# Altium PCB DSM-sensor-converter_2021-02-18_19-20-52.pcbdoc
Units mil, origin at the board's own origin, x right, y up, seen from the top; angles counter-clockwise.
Board outline 2250 x 2394.57 mil, 2 copper layers (Top Layer, Bottom Layer); 9 components, 9 nets, 34 pads, 1 vias.
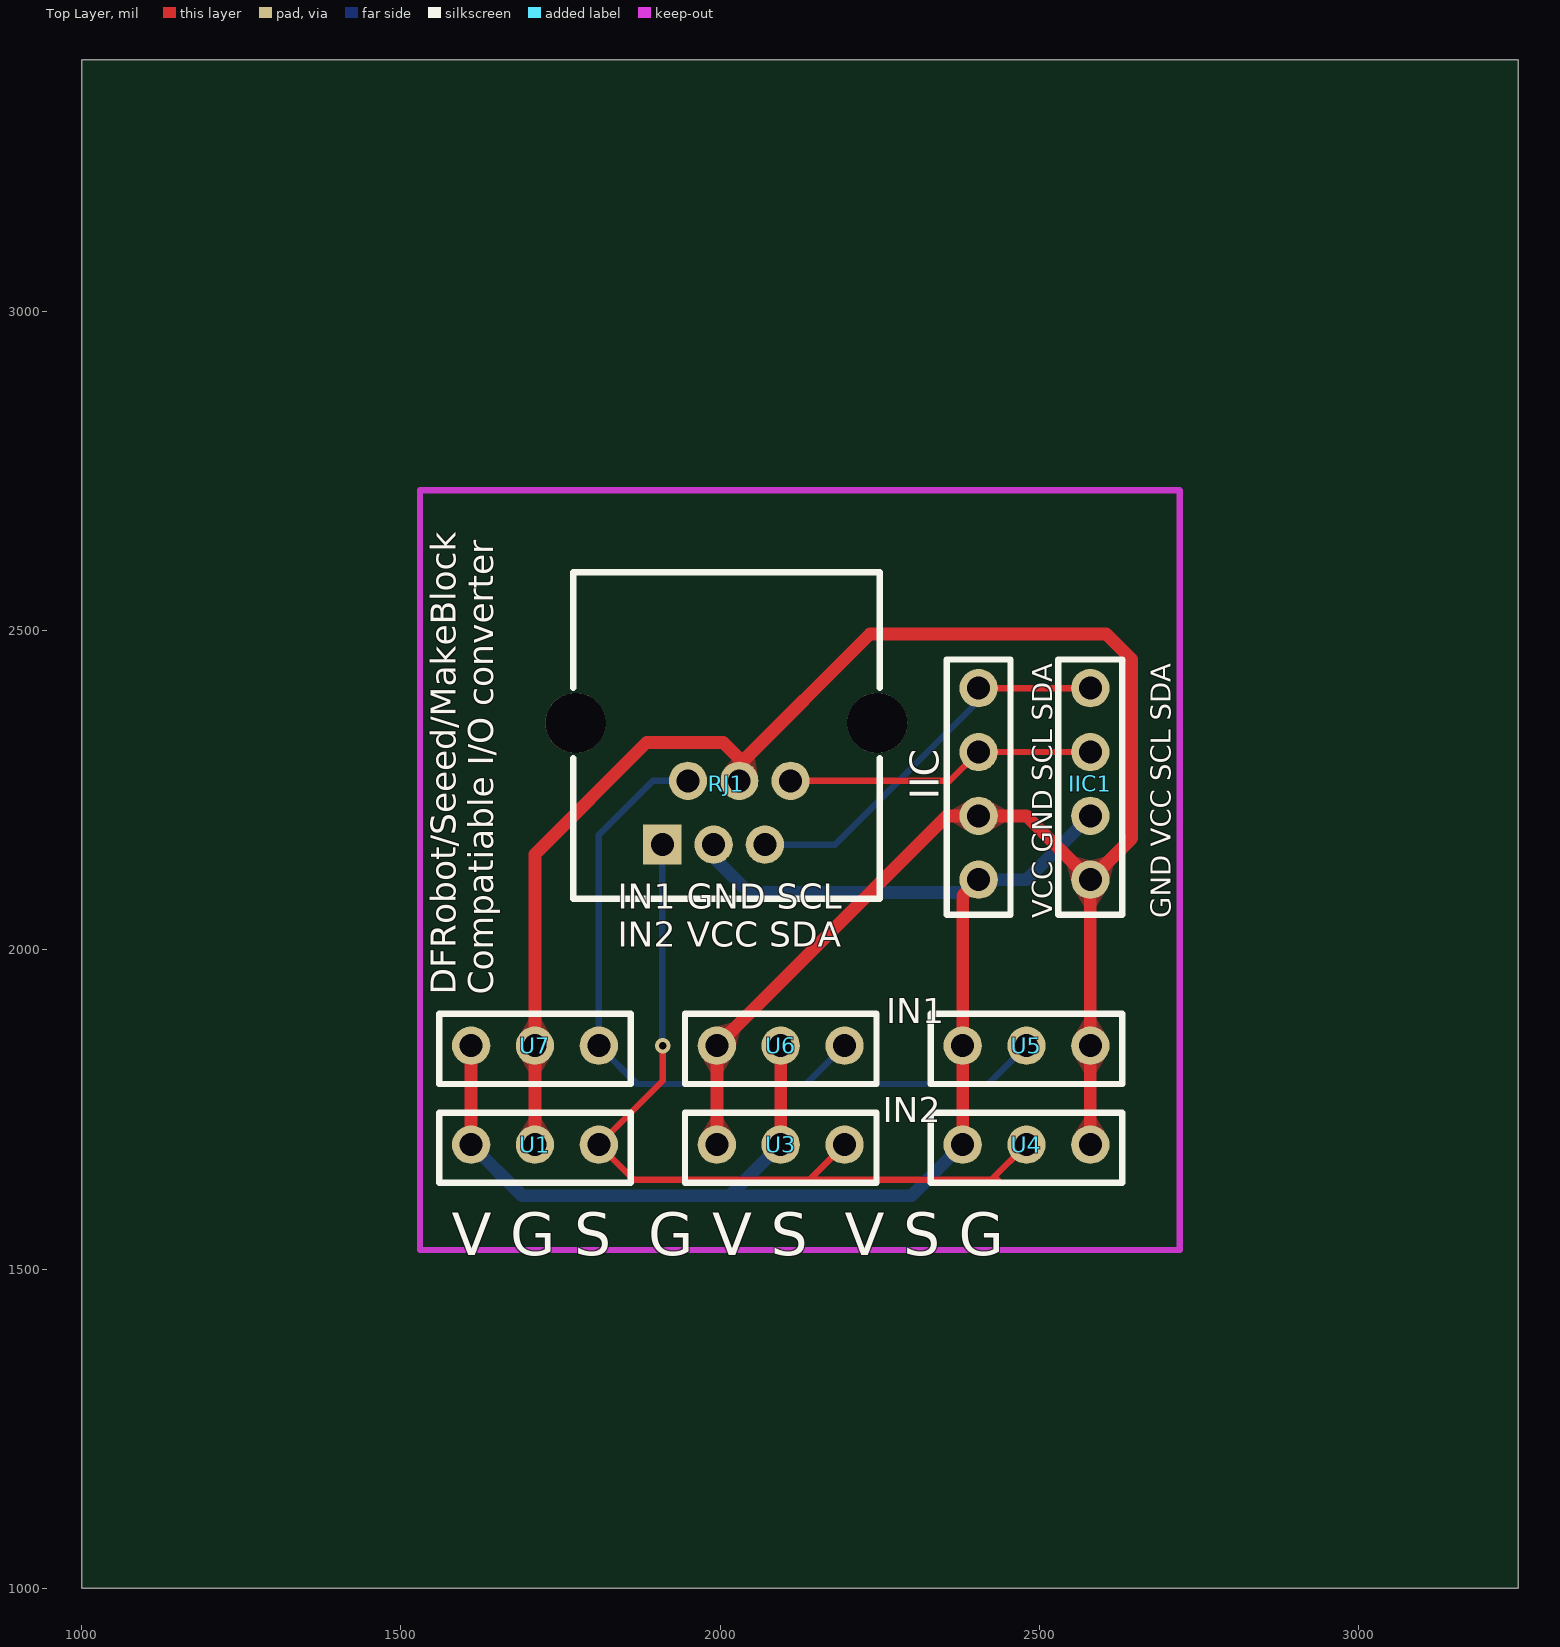
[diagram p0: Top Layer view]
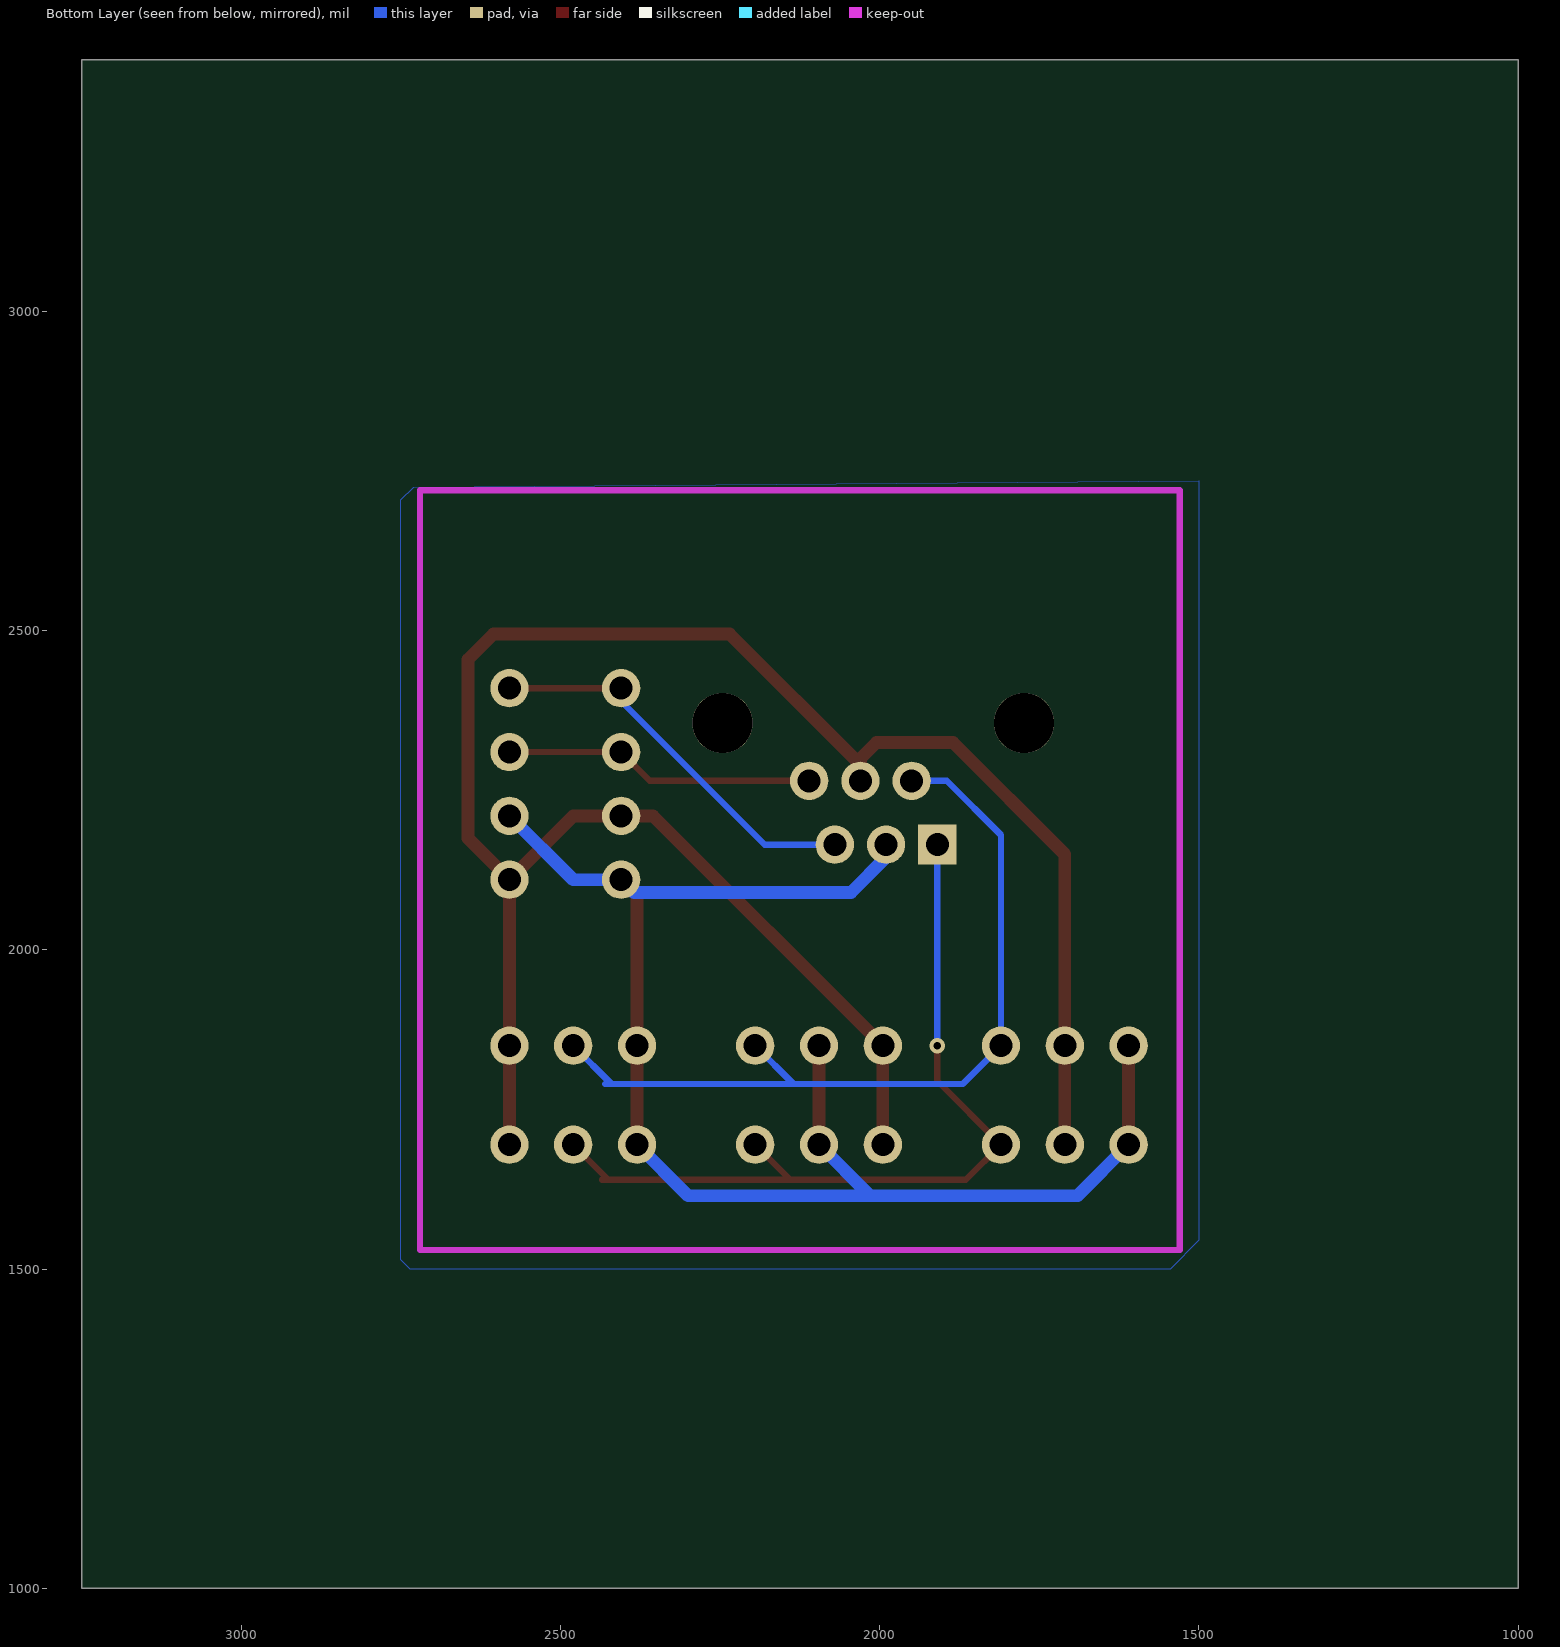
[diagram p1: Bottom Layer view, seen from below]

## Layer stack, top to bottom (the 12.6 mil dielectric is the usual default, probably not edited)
Top Layer: signal copper (thickness not stored)
Dielectric: dielectric 12.6, FR-4, Dk 4.8
Bottom Layer: signal copper (thickness not stored)

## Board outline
3250,1000 1000,1000 1000,3394.57 3250,3394.57

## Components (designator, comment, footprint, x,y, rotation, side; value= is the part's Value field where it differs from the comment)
IIC "4PIN" 4PIN 2455,2255 r90 top
IIC1 "4PIN" 4PIN 2630,2255 r90 top
RJ1 "RJ11-TH_PCB-6P6C-90" RJ11-TH_PCB-6P6C-90 2010,2215 r180 top
U1 "3PIN_2.54" 3PIN_2.54 1730,1725 r0 top
U3 "3PIN_2.54" 3PIN_2.54 2115,1725 r0 top
U4 "3PIN_2.54" 3PIN_2.54 2500,1725 r0 top
U5 "3PIN_2.54" 3PIN_2.54 2500,1880 r0 top
U6 "3PIN_2.54" 3PIN_2.54 2115,1880 r0 top
U7 "3PIN_2.54" 3PIN_2.54 1730,1880 r0 top

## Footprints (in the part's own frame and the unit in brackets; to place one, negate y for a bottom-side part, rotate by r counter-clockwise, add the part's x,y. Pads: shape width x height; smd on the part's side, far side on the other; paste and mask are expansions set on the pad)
3PIN_2.54 [mil]
  round 60 hole 35.98: ""(-120,-30) ""(-20,-30) ""(80,-30)
  silkscreen extent -170,-90 130,20
4PIN [mil]
  round 60 hole 36: 1(-145,50) 2(-45,50) 3(55,50) 4(155,50)
  silkscreen extent -200,0 200,100
RJ11-TH_PCB-6P6C-90 [mil]
  rect 60x62.99 hole 35.98: 1(100.39,50)
  round 60 hole 35.98: 2(60.23,-50) 3(20.08,50) 4(-20.08,-50) 5(-60.24,50) 6(-100.39,-50)
  round 94.49 hole 94.49 unplated: ""(-236.22,-140.55) ""(236.22,-140.55)
  silkscreen extent -240,-377 240,135

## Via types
v1: diameter 24, hole 12, Top Layer to Bottom Layer, 1 vias

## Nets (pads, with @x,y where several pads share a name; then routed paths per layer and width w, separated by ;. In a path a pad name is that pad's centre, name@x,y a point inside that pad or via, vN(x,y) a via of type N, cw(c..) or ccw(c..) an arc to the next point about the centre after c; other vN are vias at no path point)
GND: IIC1.1 IIC.2 RJ1.4 U1.@1710,1695 U3.@1995,1695 U4.@2580,1695 U5.@2580,1850 U6.@1995,1850 U7.@1710,1850 | length 3341.8
  Top Layer w20: U1.@1710,1695 1710,1850 1710,2150 1885,2325 2005,2325 2030.1,2299.9 RJ1.4 2030.08,2290.08 2235,2495 2605,2495 2645,2455 2645,2175 IIC1.1 2480,2210 IIC.2 2355,2210 1995,1850 U3.@1995,1695 ; U4.@2580,1695 U5.@2580,1850 ; IIC1.1@2580,2090 U5.@2580,1850 ; U5.@2590,1850 U5.@2580,1850
PIN1: RJ1.2
PIN2: RJ1.1 | length 1113.3
  Top Layer w10: 1810,1695 1865,1640 2140,1640 ; 2195,1695 2140,1640 ; 2425,1640 2480,1695 ; 2435,1640 2140,1640
  Bottom Layer w10: 1909.6,1855 RJ1.1
S$17: 
S$785: 
SCL: IIC1.3 IIC.3 RJ1.6 | length 488.2
  Top Layer w10: RJ1.6 2360,2265 IIC.3 IIC1.3
SDA: IIC1.4 IIC.4 RJ1.5 | length 631.3
  Top Layer w10: IIC.4 IIC1.4
  Bottom Layer w10: RJ1.5 2180,2165 IIC.4@2425,2410
SIG: U1.@1810,1695 U3.@2195,1695 U4.@2480,1695 U5.@2480,1850 U6.@2195,1850 U7.@1810,1850 | length 1516
  Top Layer w10: U1.@1810,1695 1910,1795 v1(1910,1850)
  Bottom Layer w10: 1949.8,2265 1895,2265 1810,2180 1810,1850 1870,1790 2135,1790 ; U6.@2195,1850 2135,1790 ; 2420,1790 U5.@2480,1850 ; 2430,1790 2135,1790
VCC: IIC1.2 IIC.1 RJ1.3 U1.@1610,1695 U3.@2095,1695 U4.@2380,1695 U5.@2380,1850 U6.@2095,1850 U7.@1610,1850 | length 2367.3
  Top Layer w20: U1.@1610,1695 U7.@1610,1850 ; U3.@2095,1695 U6.@2095,1850 ; U4.@2380,1695 2380,1850 2380,2085 IIC.1
  Bottom Layer w20: U1.@1610,1695 1690,1615 2015,1615 ; RJ1.3 1989.93,2145.07 2045,2090 2385,2090 IIC.1 2480,2110 IIC1.2 ; U3.@2095,1695 2015,1615 ; U4.@2380,1695 2300,1615 2015,1615
pads on no net: RJ1.

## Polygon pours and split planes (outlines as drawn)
GND on Top Layer (solid): 1505,2730 1505,1515 1510,1510 2730,1510 2740,1500 2740,2725 2735,2730
GND on Bottom Layer (solid): 1500,2735 1500,1545 1545,1500 2735,1500 2750,1515 2750,2705 2730,2725

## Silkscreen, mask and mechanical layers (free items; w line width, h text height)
Top Overlay:
  text "VCC GND SCL SDA" at 2520.75,2050 h31.5 r90
  text "GND VCC SCL SDA" at 2705.75,2050 h31.5 r90
  text "IN1 GND SCL / IN2 VCC SDA" at 1840,2005.32 h39.37
  text "DFRobot/Seeed/MakeBlock / Compatiable I/O converter" at 1644.68,1930 h39.37 r90
  text "IN1" at 2260,1885.32 h39.37
  text "IN2" at 2255,1730.32 h39.37
  text "V G S  G V S  V S G" at 1580,1521.54 h66.93
Document:
  lines w0.1: 2124,2196.28 2126,2198.28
